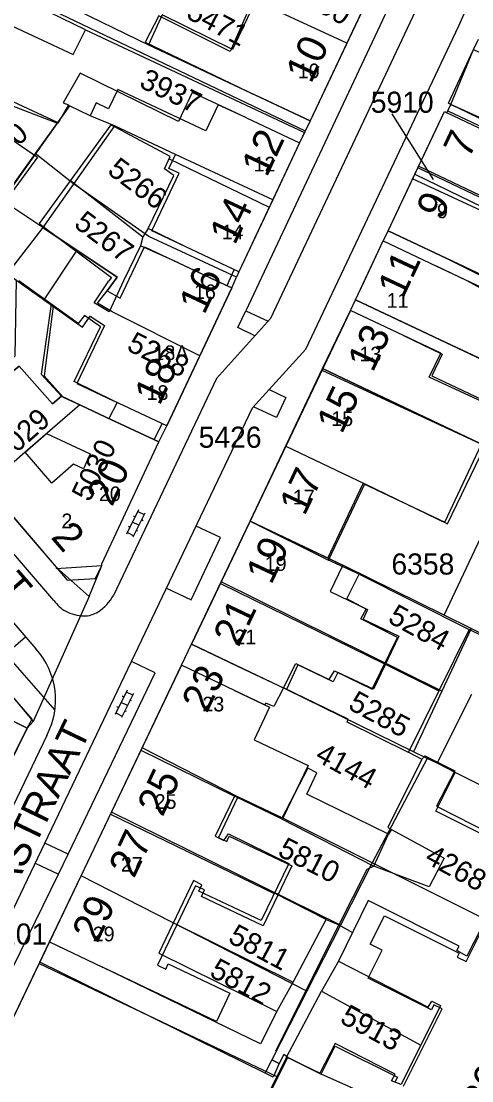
# Model space of a CAD drawing. Extents: x 148816 to 151297, y 399515 to 402500.
# Drawn here: x 150326.4 to 150364.7, y 399681.9 to 399772.1 of the extents above; entities that cross this region are included whole.
import ezdxf

# ---------------------------------------------------------------- set-up
doc = ezdxf.new("R2010")
doc.units = 0
for name, color, linetype in [('B01 Hoofdgebouw  [D] Norm', 7, 'Continuous'), ('B01 Hoofdgebouw  [T] Norm', 7, 'Continuous'), ('B01 hoofgebouw', 7, 'Continuous'), ('B02 Bijgebouw  [D] Norm', 7, 'Continuous'), ('B02 Bijgebouw  [T] Norm', 7, 'Continuous'), ('B07 Tussenmuur  [D] Norm', 7, 'Continuous'), ('G01 perceelsgrens', 7, 'Continuous'), ('S02 Open verharding  Norm', 7, 'Continuous'), ('T04 Haag heg  [D] Gem', 7, 'Continuous'), ('V00 Kant verharding algemeen  [T] Norm', 7, 'Continuous'), ('V00 Kant verharding algemeen secundair  [T] Gem', 7, 'Continuous'), ('Z01 perceelnummer', 7, 'Continuous'), ('Z02 huisnummer', 7, 'Continuous'), ('Z02 Huisnummer  [Tekst] Norm', 7, 'Continuous'), ('Z06 straatnaam', 7, 'Continuous')]:
    doc.layers.add(name, color=color, linetype=linetype)

msp = doc.modelspace()

# ---------------------------------------------------------------- linework, layer by layer
at = {"layer": 'B01 Hoofdgebouw  [D] Norm'}
msp.add_line((150364.327, 399750), (150361.69, 399751.26), dxfattribs=at)
for points in [[(150341.43, 399805.96), (150340.065, 399784.505), (150330.79, 399785.15), (150330.455, 399781.972), (150339.399, 399781.25), (150339.346, 399780.131), (150341.963, 399779.874), (150341.989, 399780.103), (150348.418, 399779.638), (150348.314, 399778.239), (150339.675, 399778.935), (150339.493, 399776.392), (150341.348, 399776.263), (150341.297, 399775.958), (150346.759, 399775.494), (150344.133, 399769.521), (150338.064, 399772.579), (150336.891, 399770.317), (150346.42, 399765.76)], [(150345.52, 399763.87), (150340.907, 399766.034), (150339.727, 399763.574), (150331.373, 399767.678), (150329.92, 399765.161), (150330.377, 399764.983), (150329.46, 399763.407), (150325.549, 399764.912), (150323.717, 399763.286), (150327.727, 399760.535), (150320.022, 399750)], [(150362.71, 399765.13), (150377.237, 399758.11), (150378.036, 399759.72), (150377.067, 399760.143), (150377.492, 399761.038), (150373.154, 399763.06), (150374.127, 399765.231), (150369.39, 399767.58)], [(150378.621, 399756.706), (150362.59, 399764.31)], [(150340.37, 399752.89), (150337.146, 399754.447), (150339.338, 399758.971), (150338.552, 399759.532), (150339.036, 399760.599), (150333.983, 399763.275), (150327.871, 399754.889), (150334.039, 399750.279), (150333.824, 399750)], [(150360.185, 399759.766), (150367.136, 399756.475), (150368.13, 399758.483), (150373.945, 399755.959), (150372.543, 399753.239), (150372.645, 399753.188), (150371.421, 399750.621), (150365.682, 399753.373), (150366.626, 399755.458), (150359.672, 399758.675)], [(150339.74, 399751.52), (150336.508, 399752.972), (150335.069, 399750)], [(150366.348, 399750), (150362.11, 399752.12)], [(150334.22, 399739.77), (150330.857, 399741.423), (150333.098, 399746.073), (150331.753, 399747.04), (150331.193, 399746.354), (150326.145, 399750)], [(150335.069, 399750), (150333.836, 399747.343), (150332.567, 399748.132), (150333.824, 399750)], [(150359.32, 399746.24), (150374.222, 399739.274), (150375.495, 399741.84), (150370.671, 399744.234), (150370.646, 399744.513), (150365.923, 399746.805), (150366.84, 399748.609), (150364.327, 399750)], [(150345.37, 399716.89), (150348.687, 399715.327), (150349.731, 399717.41), (150352.575, 399716.035), (150353.033, 399716.771), (150356.232, 399715.218), (150358.371, 399719.614), (150355.274, 399721.218), (150355.706, 399722.031), (150354.082, 399722.922), (150355.126, 399725.005), (150352.51, 399726.203), (150355.592, 399732.707), (150362.625, 399729.294), (150365.834, 399735.951), (150366.799, 399735.468), (150367.359, 399736.636), (150366.293, 399737.146), (150367.083, 399739.001), (150361.09, 399741.802), (150362.083, 399743.835), (150358.89, 399745.33)], [(150333.55, 399738.39), (150329.788, 399740.179), (150329.025, 399739.518), (150326.179, 399742.734), (150323.22, 399740.38)], [(150374.651, 399715.328), (150364.495, 399720.294), (150359.325, 399709.852), (150360.442, 399709.241), (150360.697, 399709.545), (150363.261, 399708.247), (150361.708, 399705.249), (150369.63, 399701.225)], [(150359.325, 399709.852), (150359.325, 399709.826), (150354.095, 399712.398), (150354.171, 399712.653), (150348.687, 399715.327), (150347.846, 399713.726), (150347.186, 399714.032), (150347.071, 399713.884), (150344.5, 399715.11)], [(150360.442, 399709.241), (150357.565, 399703.422), (150357.869, 399703.269), (150357.615, 399702.863), (150350.658, 399706.275), (150351.524, 399708.079), (150350.737, 399708.487), (150348.496, 399704.168), (150344.509, 399706.103), (150342.854, 399702.698), (150343.59, 399702.316), (150343.997, 399702.901), (150349.126, 399700.354), (150346.783, 399695.501), (150341.477, 399698.023), (150341.731, 399698.556), (150341.02, 399698.913), (150338.066, 399692.738), (150348.121, 399687.747), (150346.72, 399685.003), (150333.27, 399691.53)], [(150357.869, 399703.269), (150362.363, 399700.825), (150361.09, 399698.386), (150356.367, 399700.144), (150357.615, 399702.863)], [(150366.042, 399695.916), (150364.285, 399692.486), (150363.421, 399692.969), (150363.625, 399693.325), (150355.881, 399697.221), (150353.36, 399692.038), (150361.002, 399688.117), (150361.308, 399688.65), (150362.044, 399688.268), (150358.682, 399681.535), (150357.87, 399681.866), (150358.175, 399682.425), (150353.072, 399685.023), (150351.773, 399682.507), (150348.929, 399683.883), (150345.466, 399676.921)]]:
    msp.add_lwpolyline(points, dxfattribs=at)
msp.add_lwpolyline([(150324.696, 399772.11), (150330.765, 399769.28), (150331.836, 399771.39), (150326.808, 399773.812)], close=True, dxfattribs=at)
at = {"layer": 'B01 Hoofdgebouw  [T] Norm'}
for p, q in [((150357.55, 399777.62), (150350.94, 399763.63)), ((150362.71, 399765.13), (150364.86, 399769.71)), ((150350.94, 399763.63), (150346.42, 399765.76)), ((150345.52, 399763.87), (150350.04, 399761.75)), ((150357.59, 399754.25), (150362.37, 399764.41)), ((150362.37, 399764.41), (150362.59, 399764.31)), ((150350.04, 399761.75), (150344.89, 399750.77)), ((150362.11, 399752.12), (150357.59, 399754.25)), ((150344.89, 399750.77), (150340.37, 399752.89)), ((150355.57, 399750), (150357.17, 399753.39)), ((150357.17, 399753.39), (150361.69, 399751.26)), ((150339.74, 399751.52), (150342.975, 399750)), ((150344.27, 399749.39), (150338.74, 399737.64)), ((150342.975, 399750), (150344.27, 399749.39)), ((150354.8, 399748.37), (150355.57, 399750)), ((150359.32, 399746.24), (150354.8, 399748.37)), ((150354.37, 399747.48), (150340.85, 399719.04)), ((150358.89, 399745.33), (150354.37, 399747.48)), ((150338.74, 399737.64), (150334.22, 399739.77)), ((150338.08, 399736.27), (150333.55, 399738.39)), ((150319.42, 399737.14), (150329.33, 399725.61)), ((150333.22, 399725.88), (150338.08, 399736.27)), ((150329.34, 399725.5), (150333.22, 399725.75)), ((150333.22, 399725.75), (150333.22, 399725.88)), ((150329.33, 399725.61), (150329.34, 399725.5)), ((150340.85, 399719.04), (150345.37, 399716.89)), ((150339.99, 399717.26), (150328.76, 399693.68)), ((150344.5, 399715.11), (150339.99, 399717.26)), ((150324.59, 399713.03), (150326.86, 399711.89)), ((150326.86, 399711.89), (150320.14, 399698.34)), ((150328.76, 399693.68), (150333.27, 399691.53))]:
    msp.add_line(p, q, dxfattribs=at)
at = {"layer": 'B01 hoofgebouw'}
for points in [[(150360.07, 399808.22), (150359.46, 399801.28), (150358.89, 399801.31), (150358.47, 399795.59), (150359.01, 399795.55), (150357.55, 399777.62), (150350.94, 399763.63), (150346.42, 399765.76)], [(150358.332, 399787.226), (150348.667, 399787.87), (150348.306, 399782.064), (150341.679, 399782.555), (150341.544, 399781.388), (150342.547, 399781.199), (150342.395, 399779.736), (150348.289, 399779.293), (150348.062, 399777.924), (150339.43, 399778.822), (150339.24, 399776.581), (150341.127, 399776.413), (150341.08, 399775.963), (150347.332, 399776.094), (150344.338, 399769.695), (150338.336, 399772.651), (150337.186, 399770.111), (150346.42, 399765.76)], [(150362.11, 399752.12), (150357.59, 399754.25), (150362.37, 399764.41), (150362.59, 399764.31), (150362.93, 399765.03), (150362.71, 399765.13), (150364.86, 399769.71), (150369.39, 399767.58)], [(150369.39, 399767.58), (150374.249, 399765.295), (150373.178, 399763.014), (150377.378, 399761.042), (150376.782, 399759.772), (150377.803, 399759.293), (150377.407, 399758.45), (150362.93, 399765.03)], [(150345.52, 399763.87), (150343.113, 399764.999), (150342.069, 399762.78), (150334.571, 399766.308), (150333.794, 399764.656), (150332.736, 399765.154), (150332.222, 399764.062), (150330.457, 399764.893), (150321.922, 399752.903), (150331.57, 399746.056), (150332.235, 399746.982), (150333.433, 399746.204), (150331.097, 399741.241), (150334.22, 399739.77)], [(150345.52, 399763.87), (150350.04, 399761.75), (150344.89, 399750.77), (150340.37, 399752.89)], [(150362.664, 399764.466), (150375.897, 399758.24), (150374.667, 399755.625), (150368.91, 399758.333), (150366.506, 399753.225), (150372.231, 399750.531), (150371.006, 399747.928), (150362.11, 399752.12)], [(150340.37, 399752.89), (150337.471, 399754.25), (150339.787, 399759.171), (150338.924, 399759.577), (150339.474, 399760.746), (150334.288, 399763.186), (150328.203, 399754.553), (150334.511, 399750.3), (150333.68, 399749.135), (150334.78, 399748.509), (150336.839, 399752.884), (150339.74, 399751.52)], [(150359.32, 399746.24), (150354.8, 399748.37), (150357.17, 399753.39), (150361.69, 399751.26)], [(150339.74, 399751.52), (150344.27, 399749.39), (150338.74, 399737.64), (150334.22, 399739.77)], [(150361.69, 399751.26), (150366.886, 399748.812), (150365.958, 399746.847), (150370.972, 399744.481), (150370.1, 399742.634), (150371.109, 399742.157), (150370.541, 399740.952), (150359.32, 399746.24)], [(150358.89, 399745.33), (150354.37, 399747.48), (150340.85, 399719.04), (150345.37, 399716.89)], [(150358.89, 399745.33), (150362.197, 399743.757), (150361.318, 399741.909), (150367.109, 399739.156), (150366.144, 399737.127), (150367.077, 399736.683), (150366.564, 399735.604), (150352.012, 399742.519)], [(150323.22, 399740.38), (150326.179, 399742.734), (150329.025, 399739.518), (150329.788, 399740.179), (150333.55, 399738.39)], [(150323.22, 399740.38), (150319.42, 399737.14), (150329.33, 399725.61), (150329.34, 399725.5), (150333.22, 399725.75), (150333.22, 399725.88)], [(150333.22, 399725.88), (150338.08, 399736.27), (150333.55, 399738.39)], [(150328.967, 399732.776), (150326.688, 399735.409), (150328.504, 399736.981), (150332.23, 399735.26), (150331.642, 399733.988), (150330.81, 399734.372), (150328.967, 399732.776)], [(150352.45, 399726.387), (150355.45, 399732.739), (150362.408, 399729.452), (150365.543, 399736.089)], [(150345.836, 399729.529), (150353.715, 399725.786), (150352.642, 399723.53), (150355.84, 399722.01), (150355.448, 399721.185), (150358.484, 399719.742), (150356.327, 399715.206), (150353.295, 399716.648), (150352.916, 399715.851), (150349.91, 399717.28), (150348.921, 399715.201), (150345.37, 399716.89)], [(150329.33, 399725.61), (150330.26, 399724.5), (150332.67, 399724.64), (150333.22, 399725.75)], [(150311.14, 399702.93), (150320.14, 399698.34), (150326.86, 399711.89), (150324.59, 399713.03), (150325.43, 399714.8), (150322.65, 399717.98), (150315.94, 399704.69), (150312.84, 399706.27), (150311.14, 399702.93)], [(150344.5, 399715.11), (150339.99, 399717.26), (150328.76, 399693.68), (150333.27, 399691.53)], [(150344.5, 399715.11), (150347.496, 399713.682), (150346.178, 399710.913), (150350.769, 399708.726), (150348.63, 399704.234), (150344.802, 399706.057), (150343.149, 399702.586), (150343.855, 399702.25), (150344.066, 399702.692), (150349.387, 399700.157), (150346.954, 399695.048), (150341.69, 399697.554), (150341.955, 399698.11), (150341.187, 399698.476), (150337.964, 399691.71), (150338.661, 399691.378), (150338.875, 399691.829), (150344.122, 399689.33), (150342.968, 399686.907), (150333.27, 399691.53)], [(150369.514, 399700.887), (150361.648, 399704.832), (150363.3, 399708.128), (150361.762, 399708.899), (150364.717, 399714.793)], [(150358.887, 399681.387), (150362.19, 399687.974), (150361.486, 399688.327), (150361.269, 399687.894), (150355.882, 399690.595), (150357.077, 399692.976), (150356.07, 399693.481), (150357.289, 399695.912), (150363.62, 399692.738), (150363.451, 399692.401), (150364.227, 399692.012), (150365.992, 399695.532)], [(150346.419, 399678.573), (150349.06, 399683.841), (150351.887, 399682.423), (150353.087, 399684.815), (150358.372, 399682.165), (150358.163, 399681.749)], [(150347.807, 399682.163), (150347.126, 399682.504), (150347.699, 399683.646), (150348.31, 399683.34), (150347.807, 399682.163)]]:
    msp.add_lwpolyline(points, dxfattribs=at)
at = {"layer": 'B02 Bijgebouw  [D] Norm'}
for p, q in [((150334.522, 399739.628), (150333.82, 399738.264)), ((150345.839, 399729.535), (150352.51, 399726.203))]:
    msp.add_line(p, q, dxfattribs=at)
msp.add_lwpolyline([(150337.146, 399754.447), (150336.713, 399753.735), (150336.508, 399752.972)], dxfattribs=at)
at = {"layer": 'B02 Bijgebouw  [T] Norm'}
for p, q in [((150332.67, 399724.64), (150333.22, 399725.75)), ((150329.33, 399725.61), (150330.26, 399724.5)), ((150330.26, 399724.5), (150332.67, 399724.64))]:
    msp.add_line(p, q, dxfattribs=at)
at = {"layer": 'B07 Tussenmuur  [D] Norm'}
for p, q in [((150338.941, 399760.39), (150347.465, 399756.26)), ((150338.941, 399760.39), (150347.465, 399756.26)), ((150351.954, 399742.398), (150365.834, 399735.951)), ((150351.954, 399742.398), (150365.834, 399735.951)), ((150348.867, 399735.904), (150355.592, 399732.707)), ((150348.867, 399735.904), (150355.592, 399732.707)), ((150343.312, 399724.219), (150357.285, 399717.382)), ((150343.312, 399724.219), (150357.285, 399717.382)), ((150336.54, 399710.015), (150344.509, 399706.103)), ((150336.54, 399710.015), (150344.509, 399706.103)), ((150333.944, 399704.564), (150347.898, 399697.81)), ((150333.944, 399704.564), (150347.898, 399697.81))]:
    msp.add_line(p, q, dxfattribs=at)
at = {"layer": 'G01 perceelsgrens'}
for points in [[(150340.62, 399775.075), (150339.882, 399774.268), (150336.415, 399775.367), (150335.611, 399773.916), (150331.633, 399775.708), (150330.182, 399773.499), (150337.186, 399770.111), (150350.94, 399763.63)], [(150354.066, 399770.246), (150346.279, 399773.843), (150346.036, 399773.324), (150341.844, 399774.419), (150340.62, 399775.075)], [(150326.523, 399774.275), (150350.536, 399762.787)], [(150356.033, 399774.41), (150354.066, 399770.246)], [(150354.066, 399770.246), (150350.94, 399763.63)], [(150362.93, 399765.03), (150364.86, 399769.71), (150365.27, 399770.57)], [(150329.447, 399763.483), (150325.675, 399765.252)], [(150347.77, 399756.91), (150339.474, 399760.746), (150334.288, 399763.186), (150332.222, 399764.062), (150330.457, 399764.893), (150329.447, 399763.483)], [(150360.12, 399759.627), (150362.37, 399764.41), (150362.59, 399764.31), (150362.93, 399765.03)], [(150362.93, 399765.03), (150377.407, 399758.45), (150379.55, 399757.409)], [(150350.94, 399763.63), (150350.536, 399762.787)], [(150329.447, 399763.483), (150327.55, 399760.836)], [(150350.536, 399762.787), (150350.04, 399761.75), (150347.77, 399756.91)], [(150327.55, 399760.836), (150324.702, 399756.861)], [(150344.678, 399750.298), (150337.202, 399753.774), (150330.815, 399758.259), (150327.55, 399760.836)], [(150359.861, 399759.078), (150360.12, 399759.627)], [(150367.79, 399755.954), (150360.12, 399759.627)], [(150357.59, 399754.25), (150359.861, 399759.078)], [(150359.861, 399759.078), (150367.51, 399755.358), (150367.79, 399755.954)], [(150328.203, 399754.553), (150324.702, 399756.861)], [(150347.77, 399756.91), (150344.89, 399750.77), (150344.678, 399750.298)], [(150328.203, 399754.553), (150325.158, 399750.607), (150325.91, 399750.073), (150325.801, 399743.585), (150319.036, 399737.569)], [(150331.084, 399752.611), (150328.203, 399754.553)], [(150354.8, 399748.37), (150357.17, 399753.39), (150357.59, 399754.25)], [(150357.59, 399754.25), (150371.006, 399747.928), (150374.129, 399746.413)], [(150331.084, 399752.611), (150328.29, 399748.384), (150329.077, 399747.826), (150328.298, 399741.904), (150329.91, 399740.093), (150331.332, 399739.428)], [(150341.55, 399743.611), (150334.105, 399747.342), (150332.848, 399748.099), (150333.68, 399749.135), (150334.511, 399750.3), (150331.084, 399752.611)], [(150341.55, 399743.611), (150344.27, 399749.39), (150344.678, 399750.298)], [(150352.012, 399742.519), (150354.37, 399747.48), (150354.8, 399748.37)], [(150354.8, 399748.37), (150373.794, 399739.415)], [(150338.08, 399736.27), (150338.74, 399737.64), (150341.55, 399743.611)], [(150345.836, 399729.529), (150352.012, 399742.519)], [(150352.012, 399742.519), (150366.834, 399735.473), (150368.544, 399734.645)], [(150331.332, 399739.428), (150326.688, 399735.409), (150323.386, 399732.526)], [(150331.332, 399739.428), (150333.55, 399738.39), (150338.08, 399736.27)], [(150332.133, 399723.121), (150333.22, 399725.75), (150333.22, 399725.88), (150338.08, 399736.27)], [(150362.363, 399721.516), (150368.544, 399734.645)], [(150323.386, 399732.526), (150329.33, 399725.61), (150332.133, 399723.121)], [(150343.377, 399724.356), (150345.836, 399729.529)], [(150362.363, 399721.516), (150353.912, 399725.689), (150345.836, 399729.529)], [(150317.28, 399724.196), (150322.65, 399717.98), (150325.43, 399714.8), (150327.362, 399712.47)], [(150340.85, 399719.04), (150343.377, 399724.356)], [(150362.149, 399715.041), (150343.377, 399724.356)], [(150332.133, 399723.121), (150327.362, 399712.47)], [(150364.645, 399720.389), (150362.363, 399721.516)], [(150364.645, 399720.389), (150362.149, 399715.041)], [(150385.395, 399710.087), (150382.07, 399711.43), (150377.741, 399713.92), (150364.645, 399720.389)], [(150336.642, 399710.231), (150339.99, 399717.26), (150340.85, 399719.04)], [(150359.745, 399709.889), (150348.921, 399715.201), (150340.85, 399719.04)], [(150362.149, 399715.041), (150359.745, 399709.889)], [(150327.362, 399712.47), (150326.86, 399711.89), (150323.549, 399705.214)], [(150334.028, 399704.741), (150336.642, 399710.231)], [(150356.232, 399700.424), (150348.63, 399704.234), (150344.802, 399706.057), (150336.642, 399710.231)], [(150360.903, 399709.321), (150359.745, 399709.889)], [(150360.903, 399709.321), (150356.232, 399700.424)], [(150380.11, 399699.657), (150363.3, 399708.128), (150361.762, 399708.899), (150360.903, 399709.321)], [(150331.45, 399699.328), (150334.028, 399704.741)], [(150353.526, 399695.102), (150334.028, 399704.741)], [(150356.232, 399700.424), (150353.526, 399695.102)], [(150375.591, 399690.738), (150366.661, 399695.196), (150356.232, 399700.424)], [(150327.928, 399691.949), (150328.76, 399693.68), (150331.45, 399699.328)], [(150350.678, 399689.503), (150331.45, 399699.328)], [(150353.526, 399695.102), (150350.678, 399689.503)], [(150322.22, 399680.07), (150327.928, 399691.949)], [(150347.699, 399683.646), (150347.126, 399682.504), (150327.928, 399691.949)], [(150350.678, 399689.503), (150347.699, 399683.646)], [(150367.46, 399674.691), (150357.74, 399679.58), (150357.8, 399679.69), (150354.23, 399681.37), (150351.887, 399682.423), (150349.06, 399683.841), (150348.717, 399684.088), (150348.31, 399683.34), (150347.699, 399683.646)]]:
    msp.add_lwpolyline(points, dxfattribs=at)
at = {"layer": 'S02 Open verharding  Norm'}
for p, q in [((150336.335, 399730.479), (150335.322, 399728.414)), ((150336.874, 399730.214), (150335.861, 399728.149)), ((150336.269, 399730.344), (150336.808, 399730.08)), ((150336.367, 399729.182), (150335.829, 399729.446)), ((150336.049, 399729.895), (150335.914, 399729.961)), ((150336.722, 399729.565), (150336.588, 399729.631)), ((150335.388, 399728.548), (150335.927, 399728.284)), ((150335.608, 399728.997), (150335.474, 399729.063)), ((150336.282, 399728.667), (150336.147, 399728.733)), ((150335.357, 399715.123), (150334.344, 399713.058)), ((150335.291, 399714.988), (150335.83, 399714.724)), ((150335.389, 399713.826), (150334.851, 399714.09)), ((150335.896, 399714.858), (150334.883, 399712.793)), ((150335.071, 399714.539), (150334.936, 399714.605)), ((150335.744, 399714.209), (150335.61, 399714.275)), ((150334.41, 399713.192), (150334.949, 399712.928)), ((150334.63, 399713.641), (150334.496, 399713.707)), ((150335.304, 399713.311), (150335.169, 399713.377))]:
    msp.add_line(p, q, dxfattribs=at)
at = {"layer": 'T04 Haag heg  [D] Gem'}
for p, q in [((150331.836, 399771.39), (150350.456, 399762.619)), ((150327.883, 399691.855), (150348.108, 399682.233))]:
    msp.add_line(p, q, dxfattribs=at)
for points in [[(150330.533, 399758.542), (150336.713, 399753.735)], [(150328.907, 399748.017), (150328.037, 399742.036), (150329.788, 399740.179)], [(150355.126, 399725.005), (150364.495, 399720.294)], [(150357.281, 399717.374), (150361.908, 399715.07)], [(150348.496, 399704.168), (150356.367, 399700.144)], [(150356.367, 399700.144), (150355.782, 399699.865), (150353.389, 399695.139)], [(150352.322, 399695.598), (150347.906, 399697.826)], [(150339.302, 399695.321), (150349.496, 399690.262)], [(150353.389, 399695.139), (150347.99, 399684.392)], [(150349.496, 399690.262), (150352.322, 399695.598)], [(150352.322, 399695.598), (150353.389, 399695.139)], [(150353.389, 399695.139), (150354.555, 399694.494)], [(150353.36, 399692.038), (150351.908, 399689.497)], [(150348.121, 399687.747), (150349.496, 399690.262)], [(150348.929, 399683.883), (150351.908, 399689.497)], [(150351.908, 399689.497), (150360.358, 399684.892)]]:
    msp.add_lwpolyline(points, dxfattribs=at)
at = {"layer": 'V00 Kant verharding algemeen  [T] Norm'}
for p, q in [((150362.59, 399764.31), (150362.93, 399765.03)), ((150350.94, 399763.63), (150350.04, 399761.75)), ((150344.065, 399750), (150344.49, 399750.92)), ((150343.87, 399749.58), (150344.065, 399750)), ((150337.68, 399736.44), (150338.36, 399737.84)), ((150327.29, 399712.67), (150325.43, 399714.8)), ((150326.86, 399711.89), (150327.29, 399712.67)), ((150328.76, 399693.68), (150322.22, 399680.07))]:
    msp.add_line(p, q, dxfattribs=at)
for points in [[(150329.136, 399722.772), (150273.247, 399787.859)], [(150270.042, 399785.736), (150327.596, 399718.646)], [(150360.148, 399773.479), (150347.571, 399746.8), (150342.975, 399741.674), (150334.194, 399723.2)], [(150311.485, 399667.9), (150316.974, 399678.353), (150317.606, 399679.598), (150318.319, 399681.089), (150346.039, 399739.165), (150350.575, 399744.179), (150363.602, 399771.718)], [(150357.59, 399754.25), (150357.17, 399753.39)], [(150346.247, 399745.323), (150344.777, 399746.034), (150345.467, 399747.452), (150347.362, 399746.567)], [(150347.464, 399740.74), (150348.88, 399740.046), (150348.073, 399738.356), (150346.135, 399739.271)], [(150329.227, 399713.463), (150325.056, 399718.225), (150326.722, 399719.665)], [(150328.523, 399711.267), (150314.054, 399681.082), (150308.064, 399669.709)], [(150327.532, 399700.391), (150329.533, 399699.454), (150330.362, 399701.147), (150328.351, 399702.107)]]:
    msp.add_lwpolyline(points, dxfattribs=at)
for centre, radius, start, end in [((150339.554, 399782.591), 26.392, 335.6697, 355.18931), ((150330.979, 399724.92), 3.647, 301.64732, 331.84992), ((150331.511, 399724.374), 2.865, 213.9958, 241.38294), ((150331.761, 399724.895), 3.442, 241.88569, 268.53528), ((150331.716, 399723.541), 2.088, 268.80682, 304.27231), ((150322.836, 399714.3), 6.445, 331.92647, 42.39428)]:
    msp.add_arc(centre, radius, start, end, dxfattribs=at)
at = {"layer": 'V00 Kant verharding algemeen secundair  [T] Gem'}
for p, q in [((150358.213, 399774.554), (150345.467, 399747.452)), ((150323.255, 399686.668), (150329.533, 399699.454))]:
    msp.add_line(p, q, dxfattribs=at)
for points in [[(150338.715, 399723.821), (150340.811, 399722.833), (150343.318, 399728.124), (150341.239, 399729.108)], [(150330.362, 399701.147), (150337.75, 399716.607), (150335.727, 399717.561)]]:
    msp.add_lwpolyline(points, dxfattribs=at)
at = {"layer": 'Z01 perceelnummer'}
msp.add_lwpolyline([(150357.912, 399764.212), (150361.425, 399758.635)], dxfattribs=at)

# ---------------------------------------------------------------- texts
for s, rotation, p in [('5850', 330.14836, (150349.121, 399774.355)), ('5471', 332.15624, (150340.302, 399772.422)), ('3937', 334.22889, (150336.301, 399766.535)), ('3690', 41.33221, (150323.069, 399758.779)), ('5266', 323.10725, (150333.593, 399759.197)), ('5267', 323.15297, (150330.747, 399754.656)), ('5268', 333.25518, (150335.239, 399744.13)), ('5029', 41.36511, (150324.943, 399734.403)), ('5030', 64.28238, (150332.181, 399731.086)), ('5284', 331.27967, (150357.466, 399720.963)), ('5285', 331.63702, (150354.081, 399713.58)), ('4144', 331.35751, (150351.266, 399709.188)), ('5810', 332.87123, (150348.084, 399701.078)), ('4268', 331.41689, (150360.596, 399700.498)), ('5811', 331.9377, (150343.861, 399693.708)), ('5812', 331.60561, (150342.279, 399690.807)), ('5913', 331.6797, (150353.389, 399686.857))]:
    msp.add_text(s, height=1.8, rotation=rotation, dxfattribs=at).set_placement(p)
for s, p in [('5910', (150356.106, 399764.312)), ('5426', (150341.455, 399735.777)), ('6358', (150357.866, 399724.976)), ('6201', (150323.209, 399693.457))]:
    msp.add_text(s, height=1.8, dxfattribs=at).set_placement(p)
at = {"layer": 'Z02 huisnummer'}
for s, rotation, p in [('10', 64.71652, (150351.017, 399766.717)), ('12', 64.84463, (150347.25, 399758.742)), ('7', 64.84463, (150364.455, 399760.316)), ('9', 64.79278, (150362.14, 399755.111)), ('14', 64.84463, (150344.539, 399752.962)), ('11', 64.79278, (150358.841, 399748.395)), ('16', 64.79278, (150341.932, 399747.033)), ('13', 64.79278, (150356.273, 399742.121)), ('18', 64.79278, (150338.131, 399739.282)), ('15', 64.79278, (150353.643, 399736.867)), ('20', 64.97272, (150334.089, 399730.691)), ('17', 64.79278, (150350.474, 399729.894)), ('2', 310.70074, (150328.807, 399728.134)), ('19', 64.79278, (150347.637, 399724.042)), ('21', 64.53665, (150344.849, 399718.721)), ('23', 64.53665, (150342.157, 399713.093)), ('25', 64.79278, (150338.379, 399704.263)), ('27', 64.79278, (150335.955, 399699.028)), ('29', 64.53665, (150332.827, 399693.502)), ('86', 62.94832, (150365.953, 399679.04))]:
    msp.add_text(s, height=2.5, rotation=rotation, dxfattribs=at).set_placement(p)
at = {"layer": 'Z02 Huisnummer  [Tekst] Norm'}
for s, p in [('10', (150349.89, 399767.255)), ('12', (150346.135, 399759.31)), ('9', (150361.745, 399755.33)), ('14', (150343.42, 399753.525)), ('16', (150341.06, 399748.445)), ('11', (150357.457, 399747.697)), ('18A', (150337.614, 399743.241)), ('13', (150355.142, 399743.136)), ('18', (150337.02, 399739.85)), ('15', (150352.748, 399737.632)), ('20', (150332.965, 399731.235)), ('17', (150349.476, 399730.948)), ('2', (150329.775, 399728.925)), ('19', (150347.082, 399725.287)), ('21', (150344.5, 399719.035)), ('23', (150341.77, 399713.32)), ('25', (150337.708, 399705.019)), ('27', (150334.835, 399699.672)), ('29', (150332.44, 399693.735))]:
    msp.add_text(s, height=1.25, dxfattribs=at).set_placement(p)
at = {"layer": 'Z06 straatnaam'}
for s, rotation, p in [('JULIANASTRAAT', 310.74416, (150307.953, 399742.722)), ('WILHELMINASTRAAT', 64.22889, (150317.541, 399681.079))]:
    msp.add_text(s, height=2.5, rotation=rotation, dxfattribs=at).set_placement(p)

doc.saveas('drawing.dxf')
